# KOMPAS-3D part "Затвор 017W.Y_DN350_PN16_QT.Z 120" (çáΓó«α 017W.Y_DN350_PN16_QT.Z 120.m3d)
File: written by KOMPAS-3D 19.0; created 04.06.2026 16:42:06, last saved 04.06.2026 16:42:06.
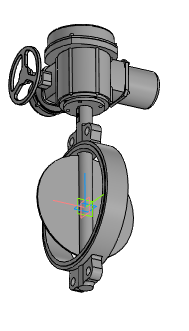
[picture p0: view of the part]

Document properties: Автор: Энергия; Полное имя файла: ..\..\..\3d для проектировщиков\017W разные\x.x Тип 017W.Y(S) Затвор дисковый поворотный межфланцевый\Затвор 017W.Y(S)_DN32-DN450_QT.Z\Затвор 017W.Y_DN350_PN16_QT.Z 120.a3d

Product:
- Part/product: Затвор 017W.Y_DN350_PN16_QT.Z 120
    Масса: 101.268

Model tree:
1. Операция без истории:1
